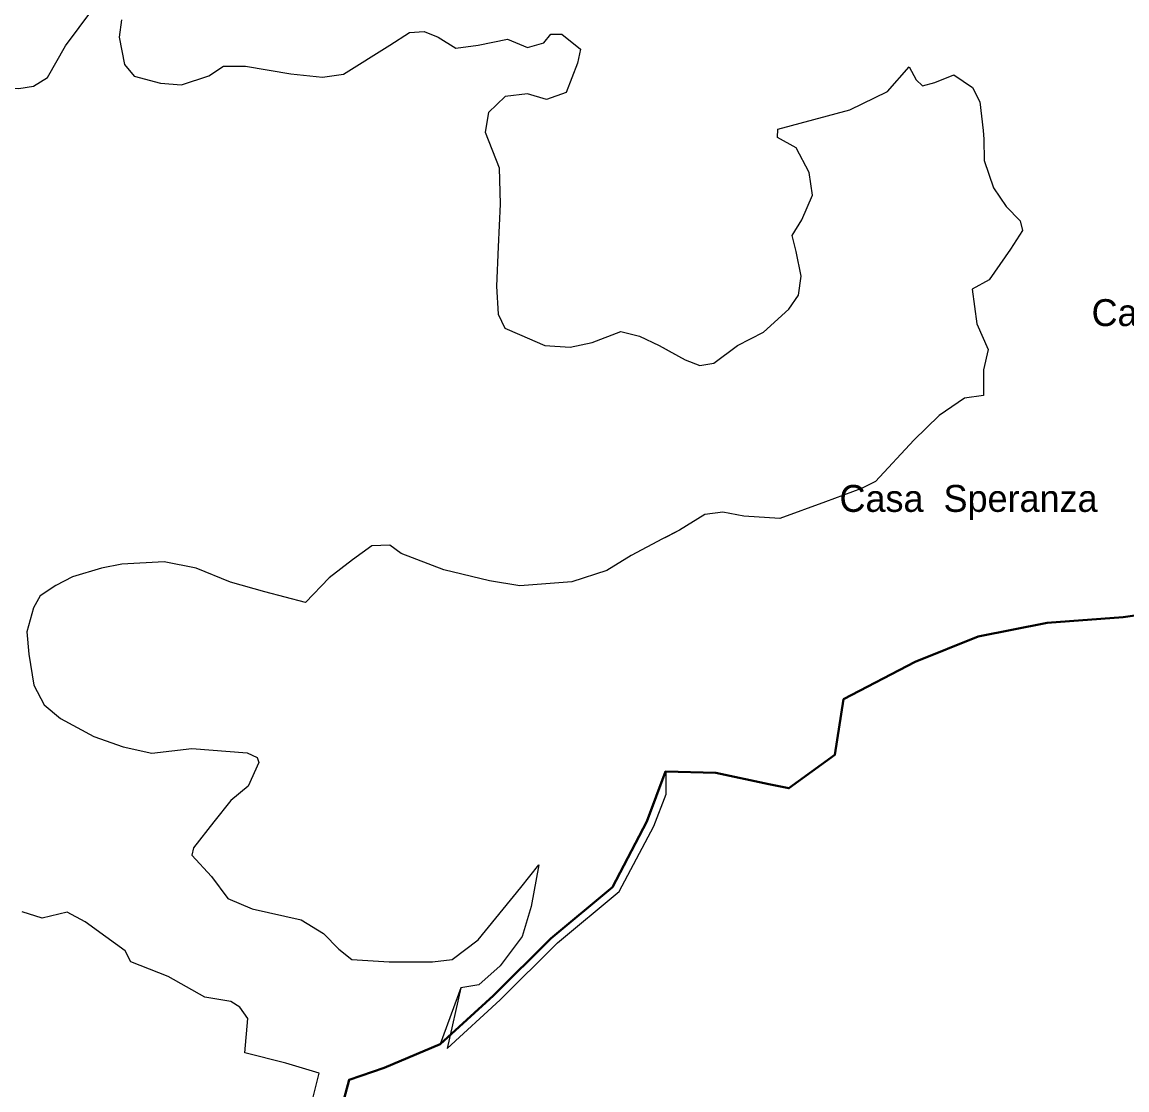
# Model space of a CAD drawing. Extents: x 645880 to 658994, y 884400 to 894744.
# Drawn here: x 656523 to 657221, y 890454 to 891129 of the extents above; entities that cross this region are included whole.
import ezdxf
from ezdxf.enums import TextEntityAlignment as Align

# ---------------------------------------------------------------- set-up
doc = ezdxf.new("R2010")
doc.units = 0
doc.header["$LTSCALE"] = 10
for name, color, linetype, lineweight in [('16', 7, 'Continuous', 25), ('18', 7, 'Continuous', 25), ('59', 7, 'Continuous', 40)]:
    doc.layers.add(name, color=color, linetype=linetype, lineweight=lineweight)
doc.layers.add('60', color=7, linetype='Continuous')

msp = doc.modelspace()

# ---------------------------------------------------------------- linework, layer by layer
at = {"layer": '16'}
for points in [[(656346.76, 891030.15), (656359.82, 891039.27), (656374.91, 891047.18), (656393.59, 891057.96), (656408.69, 891068.03), (656423.06, 891083.85), (656441.02, 891098.23), (656451.08, 891102.54), (656460.42, 891102.54), (656471.2, 891099.67), (656475.55, 891098.58), (656489.19, 891092.99), (656505.69, 891087.49), (656521.15, 891086.99), (656530.43, 891088.49), (656539.2, 891093.99), (656550.54, 891114), (656575.8, 891148.01)], [(656585.83, 891130.41), (656584.41, 891119.45), (656587.89, 891102.14), (656593.85, 891094.89), (656610.67, 891090.41), (656623.91, 891089.34), (656641.18, 891094.93), (656650.34, 891101.07), (656664.19, 891101.07), (656692.98, 891096.22), (656712.85, 891094.28), (656726.17, 891095.98), (656755.44, 891114.46), (656767.81, 891122.46), (656777.09, 891122.97), (656785.86, 891119.46), (656797.2, 891112.46), (656811.12, 891114.46), (656829.82, 891118.2), (656842.28, 891112.98), (656852.7, 891115.88), (656857.05, 891121.39), (656864, 891121.39), (656875.87, 891111.82), (656874.01, 891102.96), (656866.8, 891084.46)], [(656931.17, 890921.41), (656941.97, 890915.51), (656951.25, 890912.01), (656960.01, 890913.51), (656974.96, 890924.52), (656991.46, 890933.02), (657007.44, 890947.52), (657013.63, 890956.52), (657015.18, 890968.53), (657012.08, 890984.03), (657009.51, 890994.03), (657015.69, 891004.03), (657022.39, 891019.54), (657020.33, 891034.04), (657012.08, 891049.54), (657000.31, 891055.99), (657000.41, 891061.39), (657045.9, 891073.53), (657069.77, 891085.08), (657083.47, 891100.61), (657087.87, 891092.55), (657091.97, 891088.74), (657099.7, 891090.74), (657111.58, 891095.55), (657123.44, 891087.55), (657128.08, 891078.55), (657130.14, 891060.55), (657130.57, 891054.98), (657130.79, 891041.54), (657136.75, 891024.26), (657144.63, 891012.49), (657153.59, 891003.36), (657155.09, 890997.39), (657147.47, 890985.39), (657133.99, 890966.03), (657123.35, 890960.23), (657126.18, 890938.29), (657133.28, 890922.16), (657130.44, 890909.25), (657130.44, 890893.12)], [(656866.8, 891084.46), (656854.42, 891079.96), (656842.28, 891083.71), (656828.3, 891081.88), (656817.82, 891071.95), (656815.73, 891059.49), (656824.52, 891036.95), (656825.04, 891013.94), (656823.91, 890987.03), (656822.88, 890962.03), (656823.91, 890944.52), (656828.04, 890935.52), (656837.32, 890931.52), (656853.3, 890924.52), (656869.28, 890923.52), (656883.2, 890926.52), (656901.24, 890933.52), (656913.1, 890930.52), (656925.47, 890924.52), (656931.17, 890921.41)], [(657130.44, 890893.12), (657118.31, 890891.29), (657102.33, 890880.29), (657086.35, 890864.79), (657062.12, 890838.78), (657053.36, 890834.28), (657030.67, 890825.78), (657001.8, 890815.28), (656979.1, 890816.86), (656965.7, 890819.36), (656954.36, 890817.86), (656938.37, 890807.86), (656929.87, 890803.54), (656927.55, 890802.36), (656907.96, 890791.86), (656892.49, 890782.35), (656870.45, 890775.35), (656837.45, 890772.85), (656818.38, 890775.85), (656789.51, 890782.85), (656762.55, 890793.29), (656755.46, 890798.45), (656744.07, 890798.03), (656731.8, 890789.26), (656717.14, 890777.81), (656702.24, 890762.32), (656676.39, 890768.98), (656654.74, 890774.98), (656633.08, 890783.99), (656612.98, 890787.99), (656586.17, 890786.49), (656573.28, 890783.99), (656554.94, 890778.49), (656544.41, 890772.98), (656534.62, 890766.48), (656530.39, 890758.93), (656526.13, 890743.64), (656527.38, 890729.61), (656530.49, 890709.97), (656537.19, 890697.47)], [(656961.25, 890654.51), (656994.78, 890647.48), (657007.46, 890644.84), (657036.46, 890665.94), (657041.9, 890701.1), (657087.2, 890724.84), (657127.07, 890740.66), (657170.57, 890749.45), (657218.59, 890752.96), (657255.74, 890758.24)], [(656537.19, 890697.47), (656547.51, 890688.96), (656568.5, 890677.65), (656586.97, 890670.96), (656605.16, 890666.98), (656630.31, 890669.97), (656665.4, 890667.15), (656671.66, 890664.21), (656672.62, 890661.15), (656665.91, 890646.14), (656655.09, 890637.14), (656644.26, 890623.64), (656631.37, 890607.14), (656630.34, 890602.63), (656642.71, 890589.13), (656653.03, 890575.13), (656668.49, 890568.63), (656699.42, 890561.63), (656713.46, 890553.07), (656723.14, 890543.12), (656731.39, 890536.62), (656755.1, 890535.12), (656782.43, 890535.12), (656794.8, 890536.62), (656811.3, 890549.12), (656838.1, 890582.13), (656849.53, 890596.38), (656844.66, 890570.18), (656838.99, 890551.18), (656825.07, 890532.68), (656811.66, 890520.67), (656800.32, 890518.67), (656791.59, 890480.31), (656825.12, 890511.08), (656861.36, 890547.12), (656900.33, 890579.64), (656922.08, 890620.96), (656929.87, 890641.2), (656929.87, 890655.38), (656961.25, 890654.51)], [(656665.71, 890499.33), (656660.63, 890506.5), (656654.92, 890510.16), (656638.5, 890512.8), (656615.4, 890525.99), (656591.85, 890535.16), (656588.32, 890542.02), (656575.95, 890551.02), (656563.06, 890560.52), (656551.72, 890566.53), (656535.88, 890562.67), (656523.1, 890566.68)], [(656710.77, 890464.77), (656689.69, 890471.16), (656663.79, 890477.57), (656665.71, 890499.33)], [(656628.85, 890322.89), (656631.31, 890316.99), (656651.47, 890328.97), (656668.04, 890343.7), (656673.48, 890367.43), (656679.82, 890379.74), (656709.93, 890393.03), (656714.71, 890407.54), (656710.11, 890425.3), (656706.17, 890446.36), (656710.77, 890464.77)]]:
    msp.add_lwpolyline(points, dxfattribs=at)
at = {"layer": '18'}
for points in [[(656521.15, 891086.99), (656530.43, 891088.49), (656539.2, 891093.99), (656550.54, 891114), (656575.8, 891148.01)], [(656585.83, 891130.41), (656584.41, 891119.45), (656587.89, 891102.14), (656593.85, 891094.89), (656610.67, 891090.41), (656623.91, 891089.34), (656641.18, 891094.93), (656650.34, 891101.07), (656664.19, 891101.07), (656692.98, 891096.22), (656712.85, 891094.28), (656726.17, 891095.98), (656755.44, 891114.46), (656767.81, 891122.46), (656777.09, 891122.97), (656785.86, 891119.46), (656797.2, 891112.46), (656811.12, 891114.46)], [(656811.12, 891114.46), (656829.82, 891118.2), (656842.28, 891112.98), (656852.7, 891115.88), (656857.05, 891121.39), (656864, 891121.39), (656875.87, 891111.82), (656874.01, 891102.96), (656866.8, 891084.46), (656854.42, 891079.96), (656842.28, 891083.71), (656828.3, 891081.88), (656817.82, 891071.95), (656815.73, 891059.49), (656824.52, 891036.95), (656825.04, 891013.94), (656823.91, 890987.03), (656822.88, 890962.03), (656823.91, 890944.52), (656828.04, 890935.52), (656837.32, 890931.52), (656853.3, 890924.52), (656869.28, 890923.52), (656883.2, 890926.52), (656901.24, 890933.52), (656913.1, 890930.52), (656925.47, 890924.52), (656941.97, 890915.51), (656951.25, 890912.01), (656960.01, 890913.51), (656974.96, 890924.52), (656991.46, 890933.02), (657007.44, 890947.52), (657013.63, 890956.52), (657015.18, 890968.53), (657012.08, 890984.03), (657009.51, 890994.03), (657015.69, 891004.03), (657022.39, 891019.54), (657020.33, 891034.04)], [(657020.33, 891034.04), (657012.08, 891049.54), (657000.31, 891055.99), (657000.41, 891061.39), (657045.9, 891073.53), (657069.77, 891085.08), (657083.47, 891100.61), (657087.87, 891092.55), (657091.97, 891088.74), (657099.7, 891090.74), (657111.58, 891095.55), (657123.44, 891087.55), (657128.08, 891078.55), (657130.14, 891060.55), (657130.57, 891054.98), (657130.79, 891041.54), (657136.75, 891024.26), (657144.63, 891012.49), (657153.59, 891003.36), (657155.09, 890997.39), (657147.47, 890985.39), (657133.99, 890966.03), (657123.35, 890960.23), (657126.18, 890938.29), (657133.28, 890922.16), (657130.44, 890909.25), (657130.44, 890893.12), (657118.31, 890891.29), (657102.33, 890880.29), (657086.35, 890864.79), (657062.12, 890838.78), (657053.36, 890834.28), (657030.67, 890825.78), (657001.8, 890815.28), (656979.1, 890816.86), (656965.7, 890819.36), (656954.36, 890817.86), (656938.37, 890807.86), (656927.55, 890802.36), (656907.96, 890791.86)], [(656907.96, 890791.86), (656892.49, 890782.35), (656870.45, 890775.35), (656837.45, 890772.85), (656818.38, 890775.85), (656789.51, 890782.85), (656762.55, 890793.29), (656755.46, 890798.45), (656744.07, 890798.03), (656731.8, 890789.26), (656717.14, 890777.81), (656702.24, 890762.32), (656676.39, 890768.98), (656654.74, 890774.98), (656633.08, 890783.99), (656612.98, 890787.99), (656586.17, 890786.49), (656573.28, 890783.99), (656554.94, 890778.49), (656544.41, 890772.98), (656534.62, 890766.48), (656530.39, 890758.93), (656526.13, 890743.64), (656527.38, 890729.61), (656530.49, 890709.97), (656537.19, 890697.47), (656547.51, 890688.96), (656568.5, 890677.65), (656586.97, 890670.96), (656605.16, 890666.98), (656630.31, 890669.97), (656665.4, 890667.15), (656671.66, 890664.21), (656672.62, 890661.15), (656665.91, 890646.14), (656655.09, 890637.14), (656644.26, 890623.64), (656631.37, 890607.14), (656630.34, 890602.63), (656642.71, 890589.13)], [(656642.71, 890589.13), (656653.03, 890575.13), (656668.49, 890568.63), (656699.42, 890561.63), (656713.46, 890553.07), (656723.14, 890543.12), (656731.39, 890536.62), (656755.1, 890535.12), (656782.43, 890535.12), (656794.8, 890536.62), (656811.3, 890549.12), (656838.1, 890582.13), (656849.53, 890596.38), (656844.66, 890570.18), (656838.99, 890551.18), (656825.07, 890532.68), (656811.66, 890520.67), (656800.32, 890518.67), (656787.3, 890483.13), (656751.96, 890468.19), (656729.69, 890460.64), (656726.07, 890446.58)], [(656665.71, 890499.33), (656660.63, 890506.5), (656654.92, 890510.16), (656638.5, 890512.8), (656615.4, 890525.99), (656591.85, 890535.16), (656588.32, 890542.02), (656575.95, 890551.02), (656563.06, 890560.52), (656551.72, 890566.53), (656535.88, 890562.67), (656523.1, 890566.68)], [(656710.77, 890464.77), (656689.69, 890471.16), (656663.79, 890477.57), (656665.71, 890499.33)], [(656706.17, 890446.36), (656710.77, 890464.77)]]:
    msp.add_lwpolyline(points, dxfattribs=at)
at = {"layer": '59'}
for points in [[(657255.74, 890758.24), (657218.59, 890752.96), (657170.57, 890749.45), (657127.07, 890740.66), (657087.2, 890724.84), (657041.9, 890701.1), (657036.46, 890665.94), (657007.46, 890644.84), (656994.78, 890647.48), (656961.25, 890654.51), (656929.53, 890655.39), (656917.76, 890623.75), (656896.01, 890582.43), (656857.04, 890549.91), (656820.8, 890513.87), (656787.27, 890483.1), (656751.93, 890468.16)], [(656751.93, 890468.16), (656729.66, 890460.61), (656726.04, 890446.55)]]:
    msp.add_lwpolyline(points, dxfattribs=at)

# ---------------------------------------------------------------- texts
at = {"layer": '60'}
for s, p in [("Ca'  di  Frati", (657259.58, 890936.89)), ('Casa  Speranza', (657120.96, 890819.49))]:
    msp.add_text(s, height=17, dxfattribs=at).set_placement(p, align=Align.CENTER)

doc.saveas('drawing.dxf')
